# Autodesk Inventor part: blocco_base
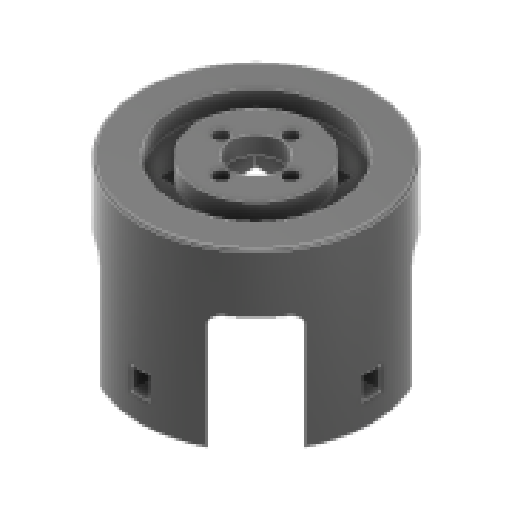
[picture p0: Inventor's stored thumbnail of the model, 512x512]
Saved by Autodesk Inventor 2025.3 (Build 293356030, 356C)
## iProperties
Created: 2026-03
Part Number: blocco_base
Material: Plastica ABS
Document SubType Name: Modeling
Designer: R5800u
Density: 1.06 g/cm^3
Appearance: Liscia - Nero
Author: R5800u
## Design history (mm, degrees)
sketch "Schizzo1"
  geometry: L1 (21, -21)-(-21, -21); L2 (-21, -21)-(-21, 21); L3 (-21, 21)-(21, 21); L4 (21, 21)-(21, -21); L5 (21, -21)-(-21, 21); L6 (-21, -21)-(21, 21); C1 r 50 at (0, 0); 1 further point
  constraints: 12 end point, 2 midpoint, 2 parallel, 1 centre point, 1 coincident, 1 horizontal, 1 perpendicular
  dimensions: "d0" = 100 diameter of C1; "d1" = 42 distance of L2.end L3.end; "d2" = 42 distance of L1.end L2.end
extrude "Estrusione1" new body sketch "Schizzo1" distance "d3" = 67.2; taper "d4" = 0 deg
sketch "Schizzo2"
  geometry: L1 (-21, 21)-(21, 21) reference; L2 (21, 21)-(21, -21) reference; L3 (21, -21)-(-21, -21) reference; L4 (-21, -21)-(-21, 21) reference; C1 r 35 at (0, 0); C2 r 50 at (0, 0) reference; C3 r 50 at (0, 0) reference; C4 r 25 at (0, 0); C5 r 11.1 at (0, 0); 1 further point
  constraints: 3 centre point, 3 coincident
  dimensions: "d5" = 70 diameter of C1; "d8" = 50 diameter of C4; "d9" = 22.2 diameter of C5
extrude "Estrusione2" join sketch "Schizzo2" distance "d6" = 10; taper "d7" = 0 deg
sketch "Schizzo3"
  geometry: C1 r 1.621 at (0, -15) reference; C2 r 1.621 at (-15, 0) reference; C3 r 1.621 at (15, 0) reference; C4 r 1.621 at (0, 15) reference; 1 further point
hole "Foro1" sketch "Schizzo3" at (-15, 0), (0, -15), (15, 0), (0, 15) diameter "d10" = 4.5; stored, may be unused: countersink angle "d14" = 82 deg, drill point angle "d16" = 118 deg; dims "d11" = 8, "d12" = 6.5, "d13" = 4.6, "d15" = 11.8
node "Piano di lavoro1"
sketch "Schizzo4"
  geometry: L1 (45.464, 2)-(46.619, 0) reference; L2 (44.309, 4)-(45.464, 2) reference; L3 (42, 4)-(44.309, 4) reference; L4 (46.619, 0)-(45.464, -2) reference; L5 (45.464, -2)-(44.309, -4) reference; L6 (44.309, -4)-(42, -4) reference; L7 (42, -4)-(39.691, -4) reference; L8 (39.691, -4)-(38.536, -2) reference; L9 (38.536, -2)-(37.381, 0) reference; L10 (37.381, 0)-(38.536, 2) reference; L11 (38.536, 2)-(39.691, 4) reference; L12 (39.691, 4)-(42, 4) reference; L13 (44.309, 4)-(49.84, 4); L14 (44.309, -4)-(49.84, -4); A1 r 50 centre (0, 0) between (49.84, 4) and (49.84, -4) reference; A2 r 50 centre (0, 0) between (49.84, 4) and (49.84, -4) reference
  constraints: 4 end point, 2 point on circle, 1 horizontal, 1 parallel
extrude "Estrusione3" cut sketch "Schizzo4" distance "d18" = 10; taper "d19" = 0 deg
sketch "Schizzo5"
  geometry: C1 r 2.65 at (65, 0) reference; 1 further point
extrude "Estrusione4" cut sketch "Schizzo5" distance "d20" = 25; taper "d21" = 0 deg
pattern_circular "Serie circolare1" dims "d23" = 360 deg
node "Piano di lavoro2"
sketch "Schizzo6"
  geometry: L1 (-50, -15)-(50, -15); L2 (50, -15)-(50, 15); L3 (50, 15)-(-50, 15); L4 (-50, 15)-(-50, -15); L5 (-50, -15)-(50, 15); L6 (50, -15)-(-50, 15); 1 further point
  constraints: 12 end point, 2 midpoint, 2 parallel, 1 horizontal, 1 perpendicular
  dimensions: "d26" = 100 distance of L3.end L2.end; "d27" = 30 distance of L2.end L1.end
extrude "Estrusione5" cut sketch "Schizzo6" extent not by distance; stored distance "d28" = 0; taper "d29" = 0 deg
pattern_circular "Serie circolare2" dims angle "d31" = 360 deg
fillet "Raccordo1" dims "d33" = 5
fillet "Raccordo2" dims "d34" = 1
node "Solido1"
node "Linea chiusa proiettata1"
node "Riferimento1"
node "Riferimento2"
node "Riferimento3"
node "Riferimento4"
node "Riferimento12"
node "Riferimento13"
node "Riferimento14"
node "Riferimento15"
node "Riferimento16"
node "Riferimento17"
node "Riferimento18"
node "Riferimento19"
node "Riferimento20"
node "Riferimento21"
node "Riferimento22"
node "Riferimento23"
node "Riferimento24"
other parameters: "d25" = 45 deg
